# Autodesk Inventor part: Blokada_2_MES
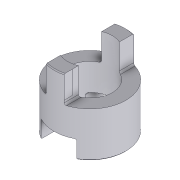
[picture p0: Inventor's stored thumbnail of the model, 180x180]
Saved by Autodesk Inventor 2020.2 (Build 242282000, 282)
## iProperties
Created: 2011-10
Part Number: Blokada_2_MES
Material: Stal
Document SubType Name: Modeling
Designer: F.Stasiak
Density: 7.85 g/cm^3
Mass: 142.719 g
Surface Area: 71.7505 cm^2
Volume: 18.1808 cm^3
Appearance: Metal-Stal
Catalog Web Link: www.expertbooks.pl
Manager: www.cadconsulting.pl
Company: Fabian Stasiak CAD Consulting
Author: F.Stasiak
Subject: Zbiór ćwiczeń. Autodesk Inventor 2020. Kurs Professional
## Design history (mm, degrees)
sketch "Szkic1"
  geometry: C1 r 20 at (0, 0); C2 r 12.5 at (0, 0); 1 further point
  constraints: 2 centre point, 2 coincident
  dimensions: "d0" = 40 diameter of C1; "d1" = 25 diameter of C2
extrude "Wyciągnięcie proste1" new body sketch "Szkic1" stored distance "d2" = 40; taper "d3" = 0 deg
sketch "Szkic2"
  geometry: L1 (-17.321, 10)-(17.321, 10); L2 (-17.321, -10)-(17.321, -10); C1 r 12.5 at (0, 0) reference; A1 r 20 centre (0, 0) between (-17.321, 10) and (17.321, 10) reference
  constraints: 4 end point, 4 point on circle, 1 collinear, 1 vertical
  dimensions: "d4" = 10 vertical distance of L1 C1.centre; "d10" = 10 vertical distance of C1.centre L2
sketch "Szkic3"
  geometry: L1 (-19.365, 5)-(19.365, 5); L2 (-19.365, -5)-(19.365, -5); C1 r 12.5 at (0, 0) reference; A1 r 20 centre (0, 0) between (-20, 0) and (20, 0) reference
  constraints: 6 point on circle, 4 end point, 1 horizontal, 1 parallel
  dimensions: "d14" = 5 distance from line of L1 C1.centre; "d15" = 5 distance from line of L2 C1.centre (= d14)
extrude "Wyciągnięcie proste3" cut sketch "Szkic3" distance "d7" = 15; taper "d8" = 0 deg
fillet "Zaokrąglenie1" dims "d9" = 1
extrude "Wyciągnięcie proste4" cut sketch "Szkic2" distance "d11" = 10; taper "d12" = 0 deg
fillet "Zaokrąglenie2" dims "d13" = 1
chamfer "Faza1" distance "d16" = 0.5; stored, may be unused: second distance "d17" = 2, angle "d18" = 45 deg
sketch "Szkic4"
  geometry: L1 (-3.583, 14.278)-(4.417, 14.278); L2 (4.417, 14.278)-(4.417, 1.278); L3 (4.417, 1.278)-(-3.583, 1.278); L4 (-3.583, 1.278)-(-3.583, 14.278); 1 further point
  constraints: 8 end point, 2 parallel, 1 horizontal, 1 perpendicular
  dimensions: "d21" = 8 distance of L1.start L1.end; "d22" = 13 distance of L3.end L1.start
feature "Podział1" sketch "Szkic4"
sketch "Szkic5"
  geometry: L1 (-2.451, -1.396)-(5.549, -1.396); L2 (5.549, -1.396)-(5.549, -14.396); L3 (5.549, -14.396)-(-2.451, -14.396); L4 (-2.451, -14.396)-(-2.451, -1.396); 1 further point
  constraints: 8 end point, 2 parallel, 1 horizontal, 1 perpendicular
  dimensions: "d19" = 8 distance of L2.end L3.end; "d20" = 13 distance of L1.end L2.end
feature "Podział2" sketch "Szkic5"
node "Bryła1"
